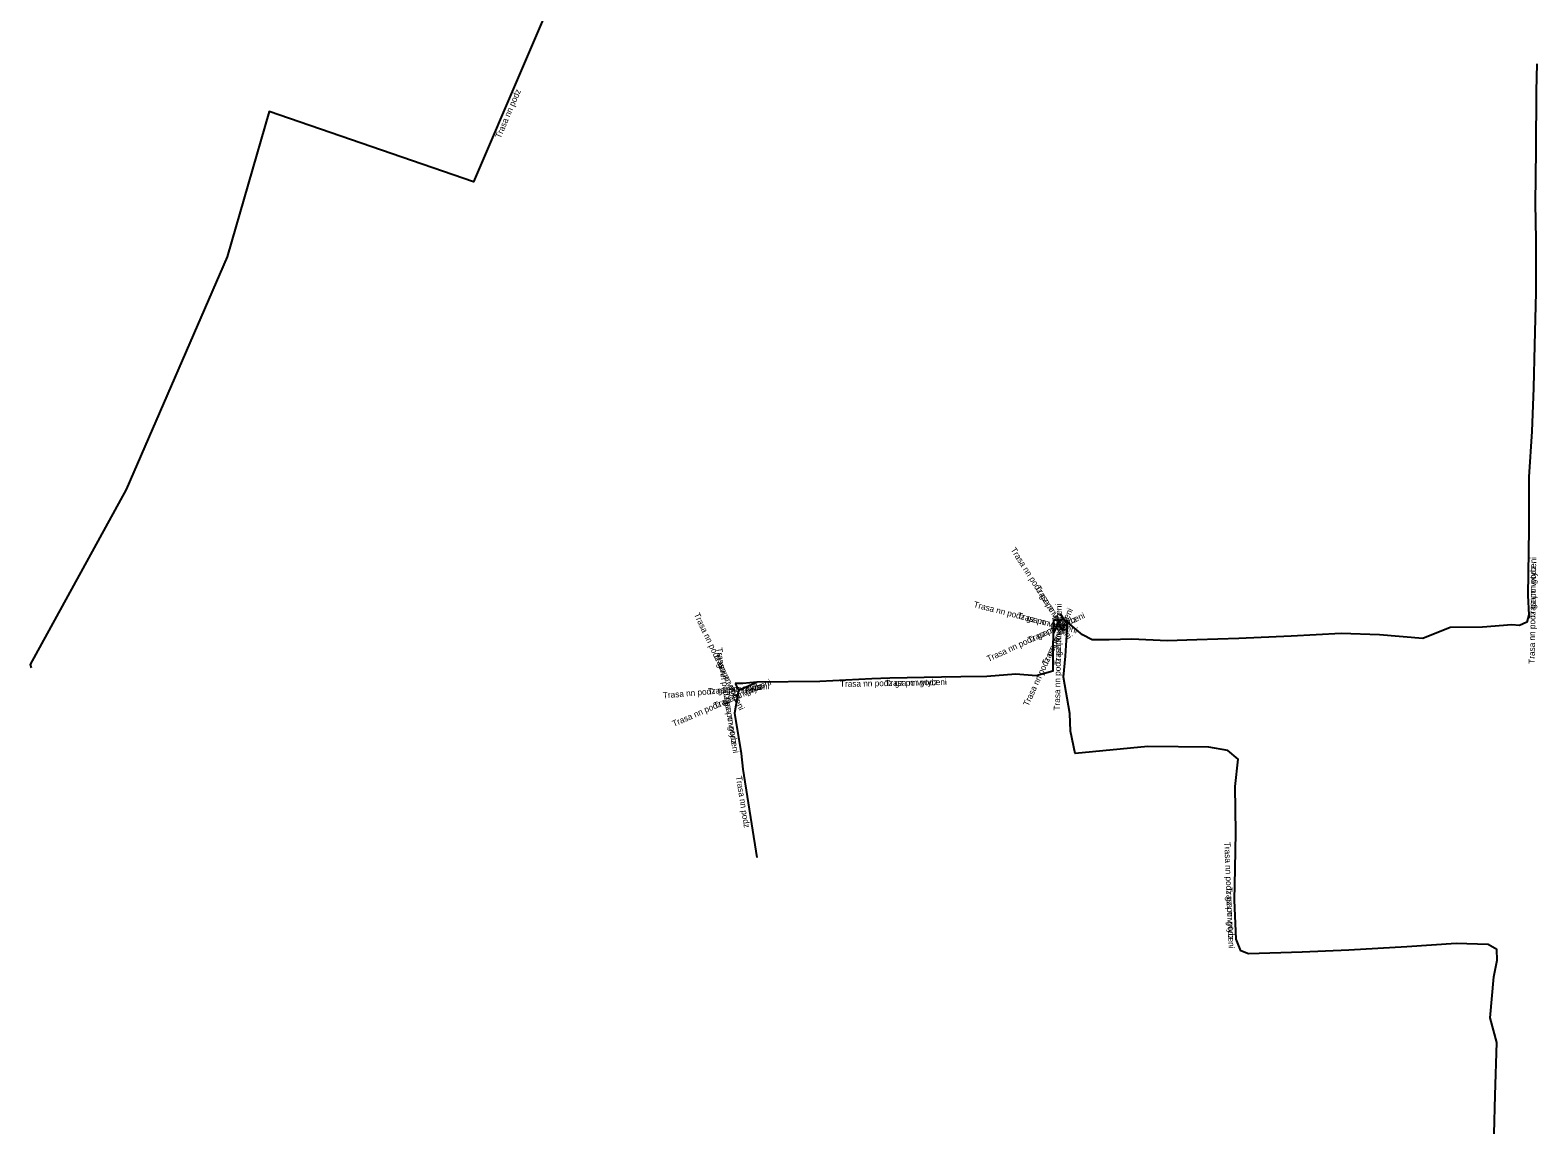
# Model space of a CAD drawing. Extents: x -876384 to -875659, y -1020218 to -1019588.
# Drawn here: x -876265.2 to -876142.3, y -1019808.2 to -1019718.3 of the extents above; entities that cross this region are included whole.
import ezdxf

# ---------------------------------------------------------------- set-up
doc = ezdxf.new("R2010")
doc.units = 0
doc.layers.add('Popiskový text - Ostatní atributy Trasy', color=7, linetype='Continuous')
doc.layers.add('Spojnice NN', color=7, linetype='Continuous')

msp = doc.modelspace()

# ---------------------------------------------------------------- linework, layer by layer
at = {"layer": 'Spojnice NN'}
for points in [[(-876240.17, -1019674.16), (-876239.75, -1019677.64), (-876216.22, -1019678.03), (-876221.2, -1019712.26), (-876229.04, -1019730.61), (-876245.68, -1019724.88), (-876249.12, -1019736.73), (-876257.34, -1019755.67), (-876265.16, -1019769.95), (-876265.09, -1019770.2)], [(-876142.43, -1019721), (-876142.48, -1019723.22), (-876142.5, -1019728.03), (-876142.54, -1019732.36), (-876142.49, -1019735.33), (-876142.51, -1019739.63), (-876142.61, -1019743.91), (-876142.69, -1019747.4), (-876142.83, -1019750.95), (-876143.07, -1019754.66), (-876143.08, -1019758.92), (-876143.16, -1019764.32), (-876143.07, -1019765.88), (-876143.24, -1019766.48), (-876143.84, -1019766.77), (-876144.44, -1019766.72), (-876146.85, -1019766.89), (-876149.47, -1019766.92), (-876151.71, -1019767.83), (-876155.24, -1019767.53), (-876158.35, -1019767.42), (-876162.43, -1019767.63), (-876166.69, -1019767.82), (-876170.11, -1019767.92), (-876172.52, -1019768), (-876175.41, -1019767.87), (-876177.27, -1019767.92), (-876178.64, -1019767.92), (-876179.43, -1019767.51), (-876180.97, -1019766.22)], [(-876142.43, -1019721), (-876142.48, -1019723.22), (-876142.5, -1019728.03), (-876142.54, -1019732.36), (-876142.49, -1019735.33), (-876142.51, -1019739.63), (-876142.61, -1019743.91), (-876142.69, -1019747.4), (-876142.83, -1019750.95), (-876143.07, -1019754.66), (-876143.08, -1019758.92), (-876143.16, -1019764.32), (-876143.07, -1019765.88), (-876143.24, -1019766.48), (-876143.84, -1019766.77), (-876144.44, -1019766.72), (-876146.85, -1019766.89), (-876149.47, -1019766.92), (-876151.71, -1019767.83), (-876155.24, -1019767.53), (-876158.35, -1019767.42), (-876162.43, -1019767.63), (-876166.69, -1019767.82), (-876170.11, -1019767.92), (-876172.52, -1019768), (-876175.41, -1019767.87), (-876177.27, -1019767.92), (-876178.64, -1019767.92), (-876179.43, -1019767.51), (-876180.97, -1019766.22)], [(-876180.97, -1019766.22), (-876181.23, -1019765.81)], [(-876180.97, -1019766.22), (-876181.23, -1019765.81)], [(-876181.79, -1019766.26), (-876181.81, -1019767.44)], [(-876181.79, -1019766.26), (-876181.81, -1019767.44)], [(-876181.32, -1019766.38), (-876181.81, -1019767.44)], [(-876181.32, -1019766.38), (-876181.81, -1019767.44)], [(-876181.79, -1019766.26), (-876181.32, -1019766.38)], [(-876181.79, -1019766.26), (-876181.32, -1019766.38)], [(-876180.97, -1019766.22), (-876181.32, -1019766.38)], [(-876180.97, -1019766.22), (-876181.32, -1019766.38)], [(-876145.89, -1019808.18), (-876145.81, -1019805.03), (-876145.68, -1019800.75), (-876146.23, -1019798.74), (-876145.93, -1019795.4), (-876145.66, -1019794.04), (-876145.68, -1019793.16), (-876146.37, -1019792.76), (-876148.98, -1019792.67), (-876153.01, -1019792.93), (-876157.74, -1019793.22), (-876161.54, -1019793.38), (-876165.9, -1019793.5), (-876166.53, -1019793.27), (-876166.91, -1019792.31), (-876167.04, -1019789.13), (-876166.99, -1019786.59), (-876166.93, -1019783.64), (-876166.98, -1019779.89), (-876166.76, -1019777.65), (-876167.6, -1019776.95), (-876169.14, -1019776.67), (-876174.12, -1019776.61), (-876180.02, -1019777.18), (-876180.42, -1019775.36), (-876180.46, -1019773.94), (-876180.98, -1019770.96), (-876180.82, -1019769.26), (-876180.66, -1019766.64), (-876180.97, -1019766.22)], [(-876145.89, -1019808.18), (-876145.81, -1019805.03), (-876145.68, -1019800.75), (-876146.23, -1019798.74), (-876145.93, -1019795.4), (-876145.66, -1019794.04), (-876145.68, -1019793.16), (-876146.37, -1019792.76), (-876148.98, -1019792.67), (-876153.01, -1019792.93), (-876157.74, -1019793.22), (-876161.54, -1019793.38), (-876165.9, -1019793.5), (-876166.53, -1019793.27), (-876166.91, -1019792.31), (-876167.04, -1019789.13), (-876166.99, -1019786.59), (-876166.93, -1019783.64), (-876166.98, -1019779.89), (-876166.76, -1019777.65), (-876167.6, -1019776.95), (-876169.14, -1019776.67), (-876174.12, -1019776.61), (-876180.02, -1019777.18), (-876180.42, -1019775.36), (-876180.46, -1019773.94), (-876180.98, -1019770.96), (-876180.82, -1019769.26), (-876180.66, -1019766.64), (-876180.97, -1019766.22)], [(-876181.81, -1019767.44), (-876181.84, -1019768.56), (-876181.85, -1019770.47), (-876183.21, -1019770.87), (-876184.87, -1019770.73), (-876187.21, -1019770.91), (-876189.35, -1019770.94), (-876190.92, -1019770.96), (-876195.13, -1019771.04), (-876196.58, -1019771.12), (-876200.83, -1019771.32), (-876205.96, -1019771.38)], [(-876181.81, -1019767.44), (-876181.84, -1019768.56), (-876181.85, -1019770.47), (-876183.21, -1019770.87), (-876184.87, -1019770.73), (-876187.21, -1019770.91), (-876189.35, -1019770.94), (-876190.92, -1019770.96), (-876195.13, -1019771.04), (-876196.58, -1019771.12), (-876200.83, -1019771.32), (-876205.96, -1019771.38)], [(-876205.96, -1019771.38), (-876207.09, -1019771.48), (-876207.72, -1019771.48)], [(-876205.96, -1019771.38), (-876207.09, -1019771.48), (-876207.72, -1019771.48)], [(-876207.72, -1019771.48), (-876207.46, -1019772.03)], [(-876207.72, -1019771.48), (-876207.46, -1019772.03)], [(-876207.46, -1019772.03), (-876205.96, -1019771.38)], [(-876207.46, -1019772.03), (-876205.96, -1019771.38)], [(-876207.46, -1019772.03), (-876207.77, -1019773.9), (-876207.24, -1019777.2), (-876207.11, -1019778.47)], [(-876207.46, -1019772.03), (-876207.77, -1019773.9), (-876207.24, -1019777.2), (-876207.11, -1019778.47)], [(-876207.11, -1019778.47), (-876205.97, -1019785.66)]]:
    msp.add_lwpolyline(points, dxfattribs=at)

# ---------------------------------------------------------------- texts
at = {"layer": 'Popiskový text - Ostatní atributy Trasy'}
for s, rotation, p in [('Trasa nn podz', 66.8755, (-876226.84, -1019727.12)), ('Trasa nn podz gz po vytyceni', 302.3807, (-876185.31, -1019760.59)), ('Trasa nn podz gz po vytyceni', 89.1512, (-876142.59, -1019769.88)), ('Trasa nn podz', 89.1512, (-876142.54, -1019766.19)), ('Trasa nn podz', 302.3807, (-876183.33, -1019763.7)), ('Trasa nn podz gz po vytyceni', 295.3014, (-876211.1, -1019765.86)), ('Trasa nn podz gz po vytyceni', 345.6773, (-876188.34, -1019765.26)), ('Trasa nn podz gz po vytyceni', 24.5672, (-876187.09, -1019769.73)), ('Trasa nn podz', 345.6773, (-876184.77, -1019766.17)), ('Trasa nn podz gz po vytyceni', 65.1906, (-876183.84, -1019773.38)), ('Trasa nn podz gz po vytyceni', 89.029, (-876181.27, -1019773.69)), ('Trasa nn podz', 89.029, (-876181.2, -1019770.01)), ('Trasa nn podz', 24.5672, (-876183.74, -1019768.2)), ('Trasa nn podz', 65.1906, (-876182.3, -1019770.04)), ('Trasa nn podz', 295.3014, (-876209.52, -1019769.19)), ('Trasa nn podz gz po vytyceni', 279.1241, (-876209.28, -1019768.6)), ('Trasa nn podz gz po vytyceni', 5.0572, (-876213.59, -1019772.71)), ('Trasa nn podz gz po vytyceni', 23.4287, (-876212.72, -1019775.02)), ('Trasa nn podz', 5.0572, (-876209.92, -1019772.38)), ('Trasa nn podz', 23.4287, (-876209.34, -1019773.55)), ('Trasa nn podz gz po vytyceni', 1.0886, (-876199.18, -1019771.77)), ('Trasa nn podz', 1.0886, (-876195.49, -1019771.7)), ('Trasa nn podz', 279.1241, (-876208.69, -1019772.24)), ('Trasa nn podz', 279.0095, (-876207.67, -1019779.06)), ('Trasa nn podz gz po vytyceni', 272.341, (-876167.88, -1019784.4)), ('Trasa nn podz', 272.341, (-876167.73, -1019788.09))]:
    msp.add_text(s, height=0.5, rotation=rotation, dxfattribs=at).set_placement(p)

doc.saveas('drawing.dxf')
